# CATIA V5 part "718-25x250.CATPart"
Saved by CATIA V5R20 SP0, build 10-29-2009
Part number: 718-25x250
Definition: NONE
Nomenclature: 718-25x250
Source: Unknown
Description: 718-25x250
Bounding box of the stored display mesh (mm): x 0 to 280, y -16 to 16, z -16 to 16
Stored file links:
  C:\Users\Utente\Desktop\IO LAVORO\3D X SITO CF\X SITO\718\718-25x250.CATPart

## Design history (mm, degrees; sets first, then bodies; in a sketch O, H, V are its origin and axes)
Body1 "718-25x250" (main body)
  Solid1: solid without history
